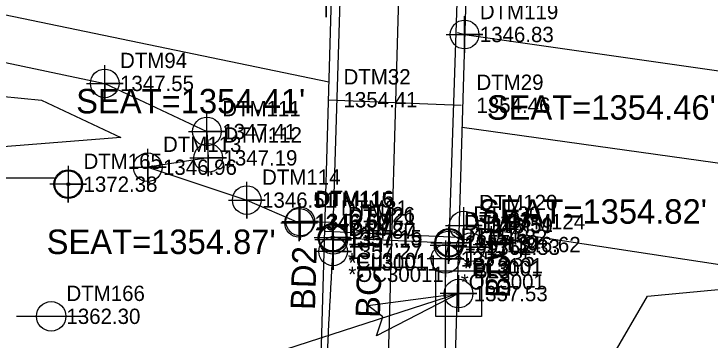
# Model space of a CAD drawing. Extents: x 1251492 to 1253015, y 859607 to 860610.
# Drawn here: x 1251972.9 to 1252086.7, y 859984.8 to 860038.1 of the extents above; entities that cross this region are included whole.
import ezdxf

# ---------------------------------------------------------------- set-up
doc = ezdxf.new("R2010")
doc.units = 0
for name, color, linetype in [('CTL Supplemental Horizontal and Vertical CELL', 7, 'Continuous'), ('Default', 7, 'Continuous'), ('Default Symbol CELL', 7, 'Continuous'), ('Default Symbol Cogo Elevation', 7, 'Continuous'), ('Default Symbol Cogo Number', 7, 'Continuous'), ('Exist Horizontal Alignment', 7, 'Continuous'), ('Exist Hydro Jurisdictional Stream or Body of Water', 7, 'Continuous'), ('Exist Hydro Stream or Body of Water', 7, 'Continuous'), ('Exist Hydro Stream or Body of Water Cogo Elevation', 7, 'Continuous'), ('Exist Hydro Stream or Body of Water Cogo Number', 7, 'Continuous'), ('Exist Hydro Stream or Body of Water Cogo Point CELL', 7, 'Continuous'), ('Exist Other Culture Located Object CELL', 7, 'Continuous'), ('Exist Other Culture Located Object Leader', 7, 'Continuous'), ('Exist Other Culture Located Object Text', 7, 'Continuous'), ('Exist Property Line', 7, 'Continuous'), ('Exist Right of Way Line', 7, 'Continuous'), ('Exist Roads EOP', 7, 'Continuous'), ('Exist Roads EOP Cogo Comment', 7, 'Continuous'), ('Exist Roads EOP Cogo Elevation', 7, 'Continuous'), ('Exist Roads EOP Cogo Number', 7, 'Continuous'), ('Exist Roads EOP Cogo Point CELL', 7, 'Continuous'), ('Exist Structure Major Bridge Seat Top Elevation', 7, 'Continuous'), ('Exist Structure Major Deck Tunnel Box Culvert', 7, 'Continuous'), ('Exist Structure Major Deck Tunnel Box Culvert Cogo Comment', 7, 'Continuous'), ('Exist Structure Major Deck Tunnel Box Culvert Cogo Elevation', 7, 'Continuous'), ('Exist Structure Major Deck Tunnel Box Culvert Cogo Number', 7, 'Continuous'), ('Exist Structure Major Deck Tunnel Box Culvert Cogo Point CELL', 7, 'Continuous'), ('Exist Utilities Power UG Cable Cogo Elevation', 7, 'Continuous'), ('Exist Utilities Power UG Cable Cogo Number', 7, 'Continuous'), ('Exist Utilities Power UG Cable Cogo Point CELL', 7, 'Continuous'), ('Exist Utilities Sanitary Sewer Manhole Cogo Elevation', 7, 'Continuous'), ('Exist Utilities Sanitary Sewer Manhole Cogo Number', 7, 'Continuous'), ('Exist Utilities Telephone Pole CELL', 7, 'Continuous'), ('Exist Utilities Telephone Pole Cogo Elevation', 7, 'Continuous'), ('Exist Utilities Telephone Pole Cogo Number', 7, 'Continuous'), ('Exist Vegetation Woods Line', 7, 'Continuous'), ('Old_Level_11', 7, 'Continuous')]:
    doc.layers.add(name, color=color, linetype=linetype)

msp = doc.modelspace()

# ---------------------------------------------------------------- linework, layer by layer
at = {"layer": 'CTL Supplemental Horizontal and Vertical CELL'}
msp.add_line((1252045.53, 859992.41), (1252045.53, 859992.41), dxfattribs=at)
msp.add_lwpolyline([(1252041.85, 859996.11), (1252049.27, 859996.11), (1252049.27, 859988.69), (1252041.85, 859988.69)], close=True, dxfattribs=at)
at = {"layer": 'Default'}
msp.add_lwpolyline([(1252045.53, 859992.41), (1251907.77, 859947.88), (1251805.02, 859947.88)], dxfattribs=at)
at = {"layer": 'Default Symbol CELL'}
msp.add_lwpolyline([(1252045.53, 859995.41), (1252045.53, 859989.41), (1252045.53, 859992.41), (1252048.53, 859992.41), (1252042.53, 859992.41)], dxfattribs=at)
msp.add_circle((1252045.53, 859992.41), 2.34, dxfattribs=at)
at = {"layer": 'Exist Horizontal Alignment'}
msp.add_line((1252033.62, 859966.57), (1252035.99, 860048.96), dxfattribs=at)
at = {"layer": 'Exist Hydro Jurisdictional Stream or Body of Water'}
for points in [[(1252046.52, 860034.73), (1252097.62, 860027.41)], [(1251923.52, 860032.49), (1251958, 860032.96), (1251987.7, 860026.74), (1252004.41, 860018.88), (1252004.61, 860014.58), (1251994.72, 860013.05), (1252010.92, 860007.68), (1252019.46, 860003.97), (1252019.67, 860004.19), (1252025.03, 860004.06)], [(1252044.14, 860003.59), (1252046.38, 860003.54), (1252090.78, 859996.8), (1252140.72, 860010.79), (1252179.76, 860006.58), (1252205.55, 860000.12)]]:
    msp.add_lwpolyline(points, dxfattribs=at)
at = {"layer": 'Exist Hydro Stream or Body of Water'}
msp.add_lwpolyline([(1252045.3, 860035.04), (1252046.52, 860034.73)], dxfattribs=at)
at = {"layer": 'Exist Hydro Stream or Body of Water Cogo Point CELL'}
for points in [[(1252020.88, 860040.56), (1252026.88, 860040.56), (1252023.88, 860040.56), (1252023.88, 860037.56), (1252023.88, 860043.56)], [(1252043.52, 860034.73), (1252049.52, 860034.73), (1252046.52, 860034.73), (1252046.52, 860031.73), (1252046.52, 860037.73)], [(1251984.7, 860026.74), (1251990.7, 860026.74), (1251987.7, 860026.74), (1251987.7, 860023.74), (1251987.7, 860029.74)], [(1252001.41, 860018.88), (1252007.41, 860018.88), (1252004.41, 860018.88), (1252004.41, 860015.88), (1252004.41, 860021.88)], [(1252001.61, 860014.58), (1252007.61, 860014.58), (1252004.61, 860014.58), (1252004.61, 860011.58), (1252004.61, 860017.58)], [(1251991.72, 860013.05), (1251997.72, 860013.05), (1251994.72, 860013.05), (1251994.72, 860010.05), (1251994.72, 860016.05)], [(1252007.92, 860007.68), (1252013.92, 860007.68), (1252010.92, 860007.68), (1252010.92, 860004.68), (1252010.92, 860010.68)], [(1252016.46, 860003.97), (1252022.46, 860003.97), (1252019.46, 860003.97), (1252019.46, 860000.97), (1252019.46, 860006.97)], [(1252016.67, 860004.19), (1252022.67, 860004.19), (1252019.67, 860004.19), (1252019.67, 860001.19), (1252019.67, 860007.19)], [(1252043.38, 860003.54), (1252049.38, 860003.54), (1252046.38, 860003.54), (1252046.38, 860000.54), (1252046.38, 860006.54)], [(1252047.91, 860000.42), (1252053.91, 860000.42), (1252050.91, 860000.42), (1252050.91, 859997.42), (1252050.91, 860003.42)]]:
    msp.add_lwpolyline(points, dxfattribs=at)
for centre in [(1252046.52, 860034.73), (1251987.7, 860026.74), (1252004.41, 860018.88), (1252004.61, 860014.58), (1251994.72, 860013.05), (1252010.92, 860007.68), (1252019.46, 860003.97), (1252019.67, 860004.19), (1252046.38, 860003.54), (1252050.91, 860000.42)]:
    msp.add_circle(centre, 2.34, dxfattribs=at)
at = {"layer": 'Exist Other Culture Located Object CELL'}
for centre, radius in [((1251981.73, 860010.28), 2.18), ((1251981.73, 860010.28), 0.24), ((1252024.95, 860001.55), 2.18), ((1252044, 860000.72), 2.18), ((1252024.95, 860001.55), 0.24), ((1252044, 860000.72), 0.24)]:
    msp.add_circle(centre, radius, dxfattribs=at)
at = {"layer": 'Exist Other Culture Located Object Leader'}
msp.add_line((1251979.48, 860011.24), (1251951.58, 860011.24), dxfattribs=at)
at = {"layer": 'Exist Property Line'}
msp.add_line((1252024.35, 860026.96), (1251971.25, 860037.95), dxfattribs=at)
msp.add_lwpolyline([(1252046.15, 860019.61), (1252097.22, 860012.47), (1252137.98, 860020.89), (1252186.95, 860018.67), (1252222.96, 860012.9)], dxfattribs=at)
at = {"layer": 'Exist Right of Way Line'}
for p, q in [((1252044.61, 859966.26), (1252046.96, 860047.77)), ((1252022.62, 859966.89), (1252024.9, 860045.92))]:
    msp.add_line(p, q, dxfattribs=at)
at = {"layer": 'Exist Roads EOP'}
for p, q in [((1252025.02, 859999.31), (1252025.06, 860001.18)), ((1252043.4, 859998.08), (1252043.92, 860000.27))]:
    msp.add_line(p, q, dxfattribs=at)
for points in [[(1252037.3, 859803.86), (1252031.99, 859851.6), (1252026.97, 859902.15), (1252023.46, 859952.27), (1252025.02, 859999.31)], [(1252056.9, 859804.94), (1252051.57, 859853.55), (1252046.86, 859903.36), (1252043.82, 859952.54), (1252043.4, 859998.08)]]:
    msp.add_spline(points, degree=3, dxfattribs=at)
at = {"layer": 'Exist Roads EOP Cogo Point CELL'}
for points in [[(1252025.06, 860004.18), (1252025.06, 859998.18), (1252025.06, 860001.18), (1252028.06, 860001.18), (1252022.06, 860001.18)], [(1252043.92, 860003.27), (1252043.92, 859997.27), (1252043.92, 860000.27), (1252046.92, 860000.27), (1252040.92, 860000.27)], [(1252047.53, 860002.98), (1252047.53, 859996.98), (1252047.53, 859999.98), (1252050.53, 859999.98), (1252044.53, 859999.98)], [(1252025.02, 860002.31), (1252025.02, 859996.31), (1252025.02, 859999.31), (1252028.02, 859999.31), (1252022.02, 859999.31)], [(1252043.4, 860001.08), (1252043.4, 859995.08), (1252043.4, 859998.08), (1252046.4, 859998.08), (1252040.4, 859998.08)]]:
    msp.add_lwpolyline(points, dxfattribs=at)
for centre in [(1252025.06, 860001.18), (1252043.92, 860000.27), (1252025.02, 859999.31), (1252047.53, 859999.98), (1252043.4, 859998.08)]:
    msp.add_circle(centre, 2.34, dxfattribs=at)
at = {"layer": 'Exist Structure Major Deck Tunnel Box Culvert'}
for p, q in [((1252024.24, 860024.07), (1252045.97, 860023.18)), ((1252023.8, 860002.63), (1252045.46, 860001.64))]:
    msp.add_line(p, q, dxfattribs=at)
msp.add_lwpolyline([(1252044, 860000.72), (1252045.51, 860046.55), (1252026.35, 860047.3), (1252024.95, 860001.55), (1252044, 860000.72)], dxfattribs=at)
at = {"layer": 'Exist Structure Major Deck Tunnel Box Culvert Cogo Point CELL'}
for points in [[(1252021.95, 860001.55), (1252027.95, 860001.55), (1252024.95, 860001.55), (1252024.95, 860004.55), (1252024.95, 859998.55)], [(1252041, 860000.72), (1252047, 860000.72), (1252044, 860000.72), (1252044, 860003.72), (1252044, 859997.72)]]:
    msp.add_lwpolyline(points, dxfattribs=at)
for centre in [(1252024.95, 860001.55), (1252044, 860000.72)]:
    msp.add_circle(centre, 2.34, dxfattribs=at)
at = {"layer": 'Exist Utilities Power UG Cable Cogo Point CELL'}
msp.add_lwpolyline([(1251981.73, 860013.28), (1251981.73, 860007.28), (1251981.73, 860010.28), (1251984.73, 860010.28), (1251978.73, 860010.28)], dxfattribs=at)
msp.add_circle((1251981.73, 860010.28), 2.34, dxfattribs=at)
at = {"layer": 'Exist Utilities Telephone Pole CELL'}
for p, q in [((1251973.27, 859988.7), (1251984.6, 859988.7)), ((1251978.94, 859988.7), (1251978.94, 859988.7))]:
    msp.add_line(p, q, dxfattribs=at)
msp.add_circle((1251978.94, 859988.7), 2.41, dxfattribs=at)
at = {"layer": 'Exist Vegetation Woods Line'}
for points in [[(1251906.04, 860030.07), (1251947.52, 860026.63), (1251950.69, 860026.63), (1251977.37, 860023.99), (1251990.31, 860017.91), (1251953.86, 860015.01), (1251946.99, 859981.44), (1251967.59, 859939.16), (1251997.44, 859888.41), (1252000.35, 859873.88), (1251996.91, 859863.57), (1251974.99, 859868.07), (1251962.31, 859871.5), (1251952.54, 859855.91), (1251959.4, 859825.52), (1251974.99, 859768.96), (1251988.99, 859729.85)], [(1252145.64, 859951.31), (1252108.13, 859957.92), (1252094.66, 859966.91), (1252070.62, 859981.97), (1252076.43, 859992.01), (1252113.41, 859995.45), (1252148.54, 860008.13), (1252186.58, 859999.15), (1252226.74, 859987.26)]]:
    msp.add_lwpolyline(points, dxfattribs=at)
at = {"layer": 'Old_Level_11'}
msp.add_lwpolyline([(1252030.69, 859990.48), (1252045.53, 859992.41), (1252032.14, 859985.52), (1252033.16, 859988.59)], close=True, dxfattribs=at)

# ---------------------------------------------------------------- texts
at = {"layer": 'Default Symbol Cogo Elevation'}
msp.add_text('1357.53', height=2.5, dxfattribs=at).set_placement((1252048.03, 859991.16))
at = {"layer": 'Default Symbol Cogo Number'}
msp.add_text('BL3', height=2.5, dxfattribs=at).set_placement((1252048.03, 859994.91))
at = {"layer": 'Exist Hydro Stream or Body of Water Cogo Elevation'}
for s, p in [('1346.83', (1252049.02, 860033.48)), ('1347.55', (1251990.2, 860025.49)), ('1347.41', (1252006.91, 860017.63)), ('1347.19', (1252007.11, 860013.33)), ('1346.96', (1251997.22, 860011.8)), ('1346.51', (1252013.42, 860006.43)), ('1346.60', (1252021.96, 860002.72)), ('1346.60', (1252022.17, 860002.95)), ('1346.59', (1252048.88, 860002.29)), ('1346.62', (1252053.41, 859999.17))]:
    msp.add_text(s, height=2.5, dxfattribs=at).set_placement(p)
at = {"layer": 'Exist Hydro Stream or Body of Water Cogo Number'}
for s, p in [('DTM119', (1252049.02, 860037.23)), ('DTM94', (1251990.2, 860029.24)), ('DTM111', (1252006.91, 860021.38)), ('DTM112', (1252007.11, 860017.08)), ('DTM113', (1251997.22, 860015.55)), ('DTM114', (1252013.42, 860010.18)), ('DTM116', (1252022.17, 860006.7)), ('DTM115', (1252021.96, 860006.47)), ('DTM120', (1252048.88, 860006.04)), ('DTM124', (1252053.41, 860002.92))]:
    msp.add_text(s, height=2.5, dxfattribs=at).set_placement(p)
at = {"layer": 'Exist Other Culture Located Object Text'}
for s, p in [('BCL1', (1252032.69, 859988.4)), ('BD1', (1252053.94, 859991.62)), ('BD2', (1252022.07, 859989.69))]:
    msp.add_text(s, height=4, rotation=88.2902, dxfattribs=at).set_placement(p)
at = {"layer": 'Exist Roads EOP Cogo Comment'}
for s, p in [('*EL30011', (1252027.56, 859996.18)), ('*OC30011', (1252027.52, 859994.31)), ('*EL3001', (1252046.42, 859995.27)), ('*OC3001', (1252045.9, 859993.08))]:
    msp.add_text(s, height=2.5, dxfattribs=at).set_placement(p)
at = {"layer": 'Exist Roads EOP Cogo Elevation'}
for s, p in [('1357.19', (1252027.56, 859999.93)), ('1357.19', (1252046.42, 859999.02)), ('1362.33', (1252050.03, 859998.73)), ('1357.27', (1252027.52, 859998.06)), ('1357.35', (1252045.9, 859996.83))]:
    msp.add_text(s, height=2.5, dxfattribs=at).set_placement(p)
at = {"layer": 'Exist Roads EOP Cogo Number'}
for s, p in [('DTM21', (1252027.56, 860003.68)), ('DTM17', (1252046.42, 860002.77)), ('DTM51', (1252050.03, 860002.48)), ('DTM20', (1252027.52, 860001.81)), ('DTM16', (1252045.9, 860000.58))]:
    msp.add_text(s, height=2.5, dxfattribs=at).set_placement(p)
at = {"layer": 'Exist Structure Major Bridge Seat Top Elevation'}
for s, p in [("SEAT=1354.41'", (1251983.03, 860021.84)), ("SEAT=1354.46'", (1252050.15, 860020.81)), ("SEAT=1354.82'", (1252048.7, 860003.82)), ("SEAT=1354.87'", (1251978.2, 859998.87))]:
    msp.add_text(s, height=4, dxfattribs=at).set_placement(p)
at = {"layer": 'Exist Structure Major Deck Tunnel Box Culvert Cogo Comment'}
for s, p in [('*CL3101', (1252027.45, 859996.55)), ('*BL3101', (1252046.5, 859995.72))]:
    msp.add_text(s, height=2.5, dxfattribs=at).set_placement(p)
at = {"layer": 'Exist Structure Major Deck Tunnel Box Culvert Cogo Elevation'}
for s, p in [('1357.15', (1252027.45, 860000.3)), ('1357.30', (1252046.5, 859999.47))]:
    msp.add_text(s, height=2.5, dxfattribs=at).set_placement(p)
at = {"layer": 'Exist Structure Major Deck Tunnel Box Culvert Cogo Number'}
for s, p in [('DTM26', (1252027.45, 860004.05)), ('DTM23', (1252046.5, 860003.22))]:
    msp.add_text(s, height=2.5, dxfattribs=at).set_placement(p)
at = {"layer": 'Exist Utilities Power UG Cable Cogo Elevation'}
msp.add_text('1372.38', height=2.5, dxfattribs=at).set_placement((1251984.23, 860009.03))
at = {"layer": 'Exist Utilities Power UG Cable Cogo Number'}
msp.add_text('DTM165', height=2.5, dxfattribs=at).set_placement((1251984.23, 860012.78))
at = {"layer": 'Exist Utilities Sanitary Sewer Manhole Cogo Elevation'}
for s, p in [('1354.41', (1252026.74, 860022.82)), ('1354.46', (1252048.47, 860021.93)), ('1354.87', (1252026.3, 860001.38)), ('1354.82', (1252047.96, 860000.39))]:
    msp.add_text(s, height=2.5, dxfattribs=at).set_placement(p)
at = {"layer": 'Exist Utilities Sanitary Sewer Manhole Cogo Number'}
for s, p in [('DTM32', (1252026.74, 860026.57)), ('DTM29', (1252048.47, 860025.68)), ('DTM31', (1252026.3, 860005.13)), ('DTM30', (1252047.96, 860004.14))]:
    msp.add_text(s, height=2.5, dxfattribs=at).set_placement(p)
at = {"layer": 'Exist Utilities Telephone Pole Cogo Elevation'}
msp.add_text('1362.30', height=2.5, dxfattribs=at).set_placement((1251981.44, 859987.45))
at = {"layer": 'Exist Utilities Telephone Pole Cogo Number'}
msp.add_text('DTM166', height=2.5, dxfattribs=at).set_placement((1251981.44, 859991.2))

doc.saveas('drawing.dxf')
